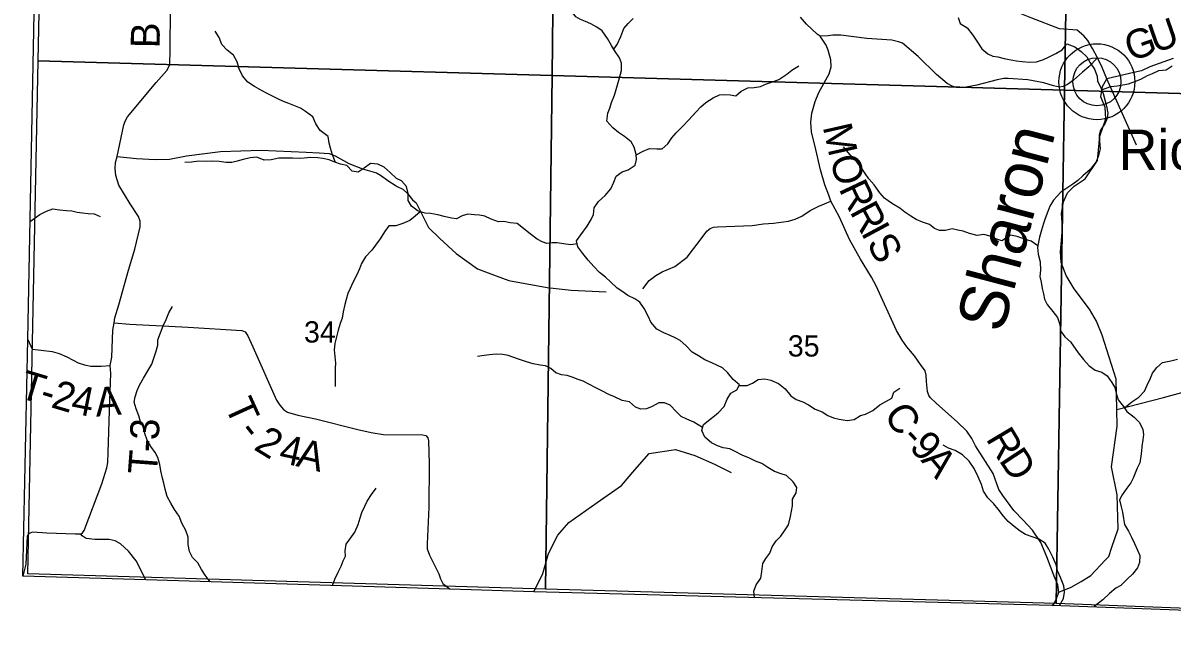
# Model space of a CAD drawing. Extents: x 2043100 to 2470832, y 443715 to 810583.
# Drawn here: x 2209669 to 2221567, y 607335 to 613550 of the extents above; entities that cross this region are included whole.
import ezdxf

# ---------------------------------------------------------------- set-up
doc = ezdxf.new("R2010")
doc.units = 0
for name, color, linetype in [('GM_X_Adjacent_County', 7, 'Continuous'), ('GM_X_County', 7, 'Continuous'), ('GM_X_County_Road', 7, 'Continuous'), ('GM_X_County_Road_Text', 7, 'Continuous'), ('GM_X_Minor_River', 7, 'Continuous'), ('GM_X_Minor_River_Text', 7, 'Continuous'), ('GM_X_Section', 7, 'Continuous'), ('GM_X_Section_Text', 7, 'Continuous'), ('GM_X_Township', 7, 'Continuous'), ('GM_X_Township_Road', 7, 'Continuous'), ('GM_X_Township_Road_Text', 7, 'Continuous'), ('GM_X_Township_ROW', 7, 'Continuous'), ('GM_X_Unincorporated', 7, 'Continuous'), ('GM_X_Unincorporated_Location', 7, 'Continuous'), ('GM_X_Unincorporated_Text', 7, 'Continuous')]:
    doc.layers.add(name, color=color, linetype=linetype)

msp = doc.modelspace()

# ---------------------------------------------------------------- linework, layer by layer
at = {"layer": 'GM_X_Adjacent_County'}
msp.add_lwpolyline([(2223684, 607391), (2220321, 607518), (2214957, 607660), (2214092, 607686), (2210942, 607782), (2209669, 607821), (2209718, 610272), (2209848, 616857), (2209978, 623419), (2210251, 634591)], dxfattribs=at)
at = {"layer": 'GM_X_County'}
msp.add_lwpolyline([(2223684, 607391), (2220321, 607518), (2214957, 607660), (2214092, 607686), (2210942, 607782), (2209669, 607821), (2209718, 610272), (2209848, 616857), (2209978, 623419), (2210251, 634591)], dxfattribs=at)
at = {"layer": 'GM_X_County_Road'}
for points in [[(2220795, 613190), (2220743, 613286), (2220694, 613369), (2220652, 613416), (2220583, 613474), (2220403, 613490), (2220115, 613598), (2219978, 613655), (2219893, 613713), (2219824, 613785), (2219797, 613838), (2219786, 613896), (2219792, 613940), (2219841, 614031), (2220009, 614316), (2220151, 614603), (2220377, 615129), (2220422, 615214), (2220495, 615322), (2220639, 615478), (2220922, 615829), (2220989, 615900), (2221175, 616039), (2221627, 616348)], [(2217922, 613414), (2217894, 613434), (2217783, 613538), (2217720, 613609)], [(2220321, 607518), (2220345, 607536), (2220368, 607584), (2220389, 607633), (2220394, 607654), (2220386, 607731), (2220348, 607819), (2220271, 608021), (2220207, 608169), (2220122, 608298), (2220026, 608400), (2219929, 608500), (2219815, 608657), (2219774, 608719), (2219715, 608885), (2219533, 609171), (2219494, 609248), (2219441, 609323), (2219346, 609414), (2219125, 609611), (2219065, 609666), (2219049, 609690), (2219034, 609733), (2219025, 609835), (2219022, 609903), (2219011, 609947), (2218963, 610014), (2218899, 610103), (2218822, 610194), (2218773, 610265), (2218714, 610366), (2218503, 610827), (2218455, 610918), (2218341, 611104), (2218229, 611306), (2218124, 611538), (2218034, 611705), (2218015, 611765), (2217972, 611872), (2217928, 612029), (2217879, 612240), (2217835, 612421), (2217828, 612523), (2217838, 612617), (2217871, 612737), (2217910, 612829), (2218017, 613024), (2218036, 613094), (2218035, 613168), (2218008, 613269), (2217985, 613319), (2217922, 613414)], [(2220795, 613190), (2220704, 613096), (2220639, 613039), (2220546, 612956), (2220483, 612913), (2220439, 612893), (2220401, 612884), (2220339, 612897), (2220239, 612930), (2220074, 612960), (2219870, 612975), (2219826, 612973), (2219755, 612962), (2219547, 612906), (2219436, 612884), (2219390, 612880), (2219334, 612883), (2219292, 612894), (2219238, 612922), (2219128, 613016), (2218940, 613201), (2218777, 613339), (2218734, 613356), (2218666, 613371), (2218406, 613390), (2218136, 613423), (2218084, 613422), (2218054, 613422), (2218006, 613415), (2217922, 613414)], [(2220892, 612972), (2220842, 613088), (2220795, 613190)], [(2221578, 613180), (2221336, 613094), (2221250, 613055), (2221170, 613036), (2220892, 612972)]]:
    msp.add_lwpolyline(points, dxfattribs=at)
at = {"layer": 'GM_X_Minor_River'}
for points in [[(2215845, 612980), (2215868, 613058), (2215868, 613134), (2215845, 613188), (2215795, 613263), (2215762, 613317), (2215722, 613389), (2215665, 613467), (2215611, 613506), (2215550, 613540), (2215492, 613565), (2215442, 613585), (2215392, 613612), (2215357, 613666), (2215293, 613718), (2215219, 613717), (2215159, 613742), (2215107, 613752), (2215035, 613771), (2214969, 613791), (2214916, 613814), (2214862, 613840), (2214763, 613873)], [(2215786, 613278), (2215820, 613326), (2215859, 613408), (2215889, 613492), (2215936, 613545), (2215986, 613595)], [(2219353, 613605), (2219374, 613543), (2219444, 613499), (2219506, 613424), (2219547, 613362), (2219596, 613282), (2219660, 613229), (2219712, 613207), (2219764, 613198), (2219830, 613180), (2219880, 613171), (2219956, 613159), (2220015, 613152), (2220093, 613142), (2220164, 613147), (2220236, 613170), (2220288, 613194), (2220364, 613233), (2220429, 613272), (2220479, 613334), (2220559, 613303), (2220627, 613255), (2220684, 613200), (2220720, 613136), (2220765, 613070)], [(2212905, 612106), (2212873, 612183), (2212852, 612253), (2212838, 612305), (2212830, 612373), (2212748, 612437), (2212702, 612505), (2212669, 612577), (2212595, 612634), (2212543, 612668), (2212475, 612696), (2212423, 612714), (2212365, 612737), (2212315, 612761), (2212245, 612795), (2212191, 612823), (2212115, 612864), (2212065, 612892), (2211997, 612938), (2211943, 613002), (2211908, 613074), (2211886, 613148), (2211848, 613215), (2211784, 613269), (2211728, 613327), (2211699, 613399), (2211659, 613465)], [(2216018, 612184), (2216092, 612221), (2216157, 612251), (2216233, 612246), (2216287, 612247), (2216347, 612299), (2216386, 612360), (2216434, 612412), (2216499, 612477), (2216564, 612545), (2216636, 612626), (2216689, 612680), (2216741, 612727), (2216816, 612776), (2216880, 612804), (2216938, 612809), (2216990, 612805), (2217052, 612796), (2217107, 612844), (2217175, 612879), (2217239, 612883), (2217307, 612890), (2217367, 612919), (2217440, 612943), (2217496, 612964), (2217578, 613019), (2217629, 613061), (2217701, 613106)], [(2220838, 612858), (2220934, 612891), (2220998, 612900), (2221056, 612909), (2221116, 612919), (2221181, 612942), (2221243, 612968), (2221313, 613005), (2221365, 613027), (2221432, 613058), (2221506, 613063), (2221570, 613105)], [(2217244, 607601), (2217237, 607665), (2217261, 607731), (2217310, 607801), (2217319, 607869), (2217331, 607952), (2217362, 608002), (2217402, 608060), (2217425, 608123), (2217468, 608185), (2217518, 608235), (2217561, 608300), (2217595, 608354), (2217618, 608440), (2217628, 608495), (2217637, 608549), (2217638, 608617), (2217674, 608683), (2217683, 608739), (2217643, 608799), (2217574, 608862), (2217520, 608882), (2217450, 608903), (2217380, 608947), (2217319, 608988), (2217253, 609010), (2217191, 609041), (2217117, 609073), (2217038, 609114), (2216988, 609140), (2216918, 609149), (2216860, 609169), (2216800, 609202), (2216731, 609259), (2216699, 609329), (2216714, 609393), (2216800, 609458), (2216869, 609513), (2216930, 609579), (2216962, 609654), (2216997, 609716), (2217059, 609749), (2217090, 609803), (2217024, 609857), (2216963, 609930), (2216911, 609978), (2216861, 610001), (2216801, 610029), (2216728, 610060), (2216664, 610104), (2216598, 610141), (2216533, 610209), (2216473, 610260), (2216421, 610288), (2216370, 610313), (2216306, 610339), (2216232, 610380), (2216169, 610452), (2216145, 610506), (2216100, 610591), (2216058, 610659), (2216003, 610694), (2215933, 610728), (2215871, 610773), (2215820, 610803), (2215754, 610870), (2215700, 610918), (2215639, 610966), (2215579, 611027), (2215522, 611093), (2215466, 611162), (2215415, 611230), (2215402, 611292), (2215446, 611356), (2215511, 611445), (2215554, 611515), (2215578, 611566), (2215585, 611636), (2215629, 611700), (2215698, 611763), (2215755, 611831), (2215787, 611902), (2215812, 611962), (2215872, 612007), (2215936, 612027), (2216007, 612076), (2216021, 612136), (2216018, 612186), (2215997, 612264), (2215965, 612320), (2215896, 612375), (2215836, 612417), (2215776, 612462), (2215715, 612534), (2215726, 612616), (2215744, 612666), (2215762, 612725), (2215793, 612803), (2215810, 612859), (2215826, 612909), (2215845, 612980)], [(2220765, 613070), (2220793, 612998), (2220796, 612948), (2220826, 612889), (2220853, 612819), (2220871, 612753), (2220888, 612689), (2220901, 612617), (2220897, 612563), (2220876, 612511), (2220828, 612438), (2220811, 612386), (2220815, 612330), (2220824, 612246), (2220807, 612176), (2220781, 612111), (2220720, 612031), (2220645, 611966), (2220593, 611919), (2220539, 611881), (2220478, 611840), (2220414, 611798), (2220339, 611715), (2220300, 611651), (2220280, 611598), (2220255, 611526), (2220235, 611472), (2220214, 611404), (2220194, 611333), (2220183, 611279), (2220175, 611225), (2220182, 611155), (2220203, 611077), (2220205, 610991), (2220198, 610923), (2220213, 610865), (2220221, 610801), (2220236, 610743), (2220248, 610689), (2220273, 610633), (2220331, 610560), (2220380, 610500), (2220406, 610426), (2220411, 610360), (2220457, 610299), (2220514, 610249), (2220595, 610134), (2220649, 610064), (2220708, 609999), (2220772, 609955), (2220840, 609934), (2220897, 609894), (2220943, 609826), (2220974, 609775), (2220988, 609717), (2221009, 609647), (2221065, 609577), (2221100, 609526), (2221174, 609468), (2221229, 609411), (2221263, 609341), (2221272, 609289), (2221266, 609233), (2221253, 609165), (2221251, 609114), (2221244, 609064), (2221232, 608994), (2221207, 608938), (2221185, 608888), (2221166, 608837), (2221142, 608787), (2221099, 608733), (2221049, 608664), (2221024, 608610), (2221041, 608540), (2221055, 608484), (2221064, 608418), (2221076, 608356), (2221115, 608287), (2221147, 608225), (2221178, 608159), (2221208, 608089), (2221233, 608035), (2221229, 607963), (2221208, 607907), (2221157, 607843), (2221101, 607788), (2221038, 607725), (2220986, 607695), (2220919, 607640), (2220849, 607574), (2220760, 607505)], [(2220178, 611243), (2220109, 611289), (2220039, 611310), (2219965, 611339), (2219893, 611351), (2219803, 611294), (2219741, 611313), (2219685, 611341), (2219617, 611358), (2219549, 611348), (2219469, 611369), (2219403, 611393), (2219348, 611404), (2219290, 611418), (2219221, 611399), (2219159, 611402), (2219109, 611422), (2219056, 611462), (2218982, 611485), (2218916, 611514), (2218862, 611548), (2218801, 611590), (2218747, 611631), (2218691, 611667), (2218640, 611698), (2218588, 611736), (2218540, 611792), (2218481, 611873), (2218428, 611935), (2218390, 611990), (2218356, 612042), (2218301, 612114), (2218230, 612189), (2218166, 612267)], [(2214787, 611472), (2214715, 611481), (2214649, 611493), (2214593, 611489), (2214517, 611518), (2214451, 611548), (2214397, 611560), (2214343, 611564), (2214275, 611571), (2214217, 611553), (2214157, 611521), (2214105, 611529), (2214031, 611546), (2213965, 611562), (2213889, 611576), (2213835, 611581), (2213761, 611599), (2213693, 611653), (2213659, 611711), (2213659, 611783), (2213639, 611855), (2213587, 611914), (2213536, 611938), (2213472, 612002), (2213410, 612058), (2213344, 612086), (2213268, 612093), (2213203, 612045), (2213139, 612003), (2213077, 612014), (2213021, 612072), (2212957, 612088), (2212897, 612109), (2212841, 612133), (2212775, 612147), (2212721, 612153), (2212651, 612158), (2212581, 612150), (2212529, 612146), (2212459, 612148), (2212397, 612149), (2212317, 612151), (2212240, 612133), (2212166, 612130), (2212092, 612160), (2212022, 612154), (2211948, 612135), (2211886, 612119), (2211830, 612105), (2211772, 612106), (2211701, 612116), (2211631, 612120), (2211569, 612115), (2211489, 612119), (2211415, 612109), (2211345, 612106)], [(2209746, 611498), (2209843, 611567), (2209911, 611600), (2209977, 611624), (2210047, 611616), (2210121, 611609), (2210175, 611603), (2210229, 611589), (2210285, 611583), (2210345, 611578), (2210405, 611574), (2210467, 611546)], [(2213781, 611594), (2213730, 611549), (2213676, 611503), (2213602, 611472), (2213530, 611450), (2213459, 611450), (2213411, 611385), (2213367, 611315), (2213318, 611247), (2213280, 611197), (2213216, 611126), (2213174, 611058), (2213153, 611004), (2213121, 610934), (2213085, 610862), (2213058, 610800), (2213034, 610749), (2213014, 610685), (2213000, 610633), (2212983, 610557), (2212973, 610491), (2212953, 610437), (2212932, 610367), (2212916, 610299), (2212898, 610231), (2212890, 610164), (2212899, 610094), (2212905, 610028), (2212903, 609974), (2212901, 609908), (2212900, 609858), (2212900, 609784)], [(2215408, 611264), (2215343, 611253), (2215267, 611263), (2215201, 611272), (2215149, 611272), (2215095, 611267), (2215045, 611283), (2214993, 611310), (2214920, 611366), (2214787, 611472)], [(2211607, 607763), (2211556, 607832), (2211519, 607891), (2211479, 607959), (2211425, 608013), (2211393, 608075), (2211381, 608147), (2211380, 608223), (2211356, 608295), (2211314, 608371), (2211286, 608441), (2211237, 608510), (2211199, 608578), (2211163, 608646), (2211143, 608720), (2211128, 608784), (2211114, 608836), (2211098, 608910), (2211086, 608978), (2211064, 609048), (2211037, 609102), (2210993, 609165), (2210955, 609229), (2210931, 609297), (2210921, 609353), (2210886, 609419), (2210868, 609481), (2210840, 609553), (2210822, 609621), (2210831, 609677), (2210851, 609743), (2210875, 609797), (2210917, 609871), (2210962, 609946), (2211004, 610016), (2211024, 610080), (2211045, 610140), (2211065, 610212), (2211065, 610268), (2211092, 610342), (2211120, 610413), (2211150, 610479), (2211179, 610547), (2211217, 610613)], [(2214800, 610067), (2214694, 610107), (2214638, 610116), (2214568, 610120), (2214498, 610114), (2214446, 610106), (2214374, 610095)], [(2216706, 609360), (2216616, 609417), (2216544, 609448), (2216486, 609474), (2216433, 609527), (2216369, 609593), (2216313, 609616), (2216253, 609616), (2216185, 609579), (2216127, 609555), (2216067, 609550), (2216013, 609570), (2215949, 609625), (2215875, 609640), (2215794, 609678), (2215736, 609703), (2215662, 609739), (2215600, 609770), (2215535, 609806), (2215469, 609839), (2215419, 609859), (2215355, 609882), (2215305, 609900), (2215245, 609907), (2215187, 609927), (2215134, 609970), (2215078, 609998), (2215024, 610007), (2214952, 610019), (2214882, 610042), (2214800, 610067)], [(2221074, 609565), (2221151, 609626), (2221222, 609675), (2221282, 609737), (2221311, 609800), (2221343, 609870), (2221366, 609922), (2221408, 609981), (2221467, 610035), (2221553, 610052), (2221625, 610067)], [(2217086, 609796), (2217166, 609794), (2217224, 609818), (2217280, 609857), (2217352, 609865), (2217412, 609852), (2217492, 609817), (2217562, 609759), (2217621, 609688), (2217675, 609650), (2217743, 609627), (2217802, 609595), (2217872, 609550), (2217944, 609524), (2218004, 609485), (2218061, 609461), (2218121, 609448), (2218203, 609432), (2218277, 609443), (2218340, 609486), (2218394, 609498), (2218468, 609537), (2218541, 609595), (2218664, 609665), (2218688, 609725), (2218749, 609769)], [(2220401, 607517), (2220443, 607588), (2220455, 607654), (2220446, 607720), (2220413, 607806), (2220383, 607870), (2220368, 607938), (2220332, 608016), (2220293, 608099), (2220252, 608161), (2220188, 608204), (2220130, 608224), (2220048, 608253), (2219994, 608287), (2219931, 608336), (2219871, 608388), (2219822, 608442), (2219768, 608513), (2219723, 608569), (2219659, 608632), (2219614, 608700), (2219594, 608770), (2219561, 608850), (2219518, 608935), (2219468, 609013), (2219399, 609076), (2219323, 609122), (2219251, 609145), (2219198, 609179)], [(2212875, 607724), (2212898, 607788), (2212931, 607862), (2212965, 607924), (2212985, 607978), (2213007, 608028), (2213006, 608084), (2213016, 608152), (2213070, 608227), (2213106, 608277), (2213139, 608355), (2213159, 608425), (2213177, 608479), (2213210, 608547), (2213234, 608597), (2213278, 608668), (2213327, 608732)]]:
    msp.add_lwpolyline(points, dxfattribs=at)
at = {"layer": 'GM_X_Section'}
for points in [[(2215204, 618338), (2215147, 613006), (2209825, 613158), (2209936, 618484)], [(2215204, 618338), (2220542, 618152), (2220453, 612855), (2215147, 613006)], [(2225918, 617981), (2225830, 612699), (2220453, 612855), (2220542, 618152)], [(2209825, 613158), (2215147, 613006), (2215081, 607686), (2209719, 607845)], [(2215147, 613006), (2220453, 612855), (2220366, 607536), (2215081, 607686)], [(2225830, 612699), (2225736, 607335), (2220366, 607536), (2220453, 612855)]]:
    msp.add_lwpolyline(points, close=True, dxfattribs=at)
at = {"layer": 'GM_X_Township'}
msp.add_lwpolyline([(2223684, 607391), (2220321, 607518), (2214957, 607660), (2214092, 607686), (2210942, 607782), (2209669, 607821), (2209718, 610272), (2209848, 616857), (2209978, 623419), (2210251, 634591)], dxfattribs=at)
at = {"layer": 'GM_X_Township_Road'}
for points in [[(2210612, 610444), (2210612, 610444), (2210620, 610496), (2210660, 610632), (2210762, 610991), (2210826, 611207), (2210883, 611440), (2210882, 611496), (2210864, 611547), (2210780, 611678), (2210662, 611871), (2210631, 611970), (2210624, 612044), (2210628, 612106), (2210643, 612168), (2210713, 612493), (2210731, 612541), (2210752, 612577), (2211048, 612934), (2211157, 613057), (2211181, 613095), (2211188, 613121), (2211193, 613273), (2211198, 613694)], [(2221200, 612283), (2220892, 612972)], [(2210573, 610004), (2210590, 610088), (2210599, 610368), (2210612, 610444)], [(2210612, 610444), (2210776, 610432), (2211379, 610400), (2211934, 610364), (2211968, 610350), (2211996, 610311), (2212048, 610197), (2212294, 609643), (2212327, 609591), (2212365, 609546), (2212409, 609520), (2212516, 609489), (2212698, 609449), (2213136, 609340), (2213276, 609307), (2213402, 609289), (2213811, 609285), (2213839, 609277), (2213861, 609254), (2213867, 609222), (2213874, 608984), (2213873, 608535), (2213853, 608155), (2213854, 608105), (2213879, 608039), (2213975, 607844), (2213993, 607793), (2214016, 607745), (2214092, 607686)], [(2209718, 610272), (2209765, 610171), (2209857, 610160), (2209971, 610147), (2210044, 610128), (2210122, 610093), (2210188, 610056), (2210241, 610030), (2210305, 610009), (2210373, 609996), (2210477, 609997), (2210573, 610004)], [(2210267, 608257), (2210287, 608271), (2210302, 608293), (2210487, 608776), (2210539, 608943), (2210546, 608997), (2210551, 609101), (2210569, 609640), (2210578, 609918), (2210573, 610004)], [(2210267, 608257), (2210213, 608256), (2209916, 608267), (2209768, 608277), (2209750, 608271), (2209730, 608261), (2209713, 608235), (2209698, 607945), (2209669, 607821)], [(2220394, 607654), (2220524, 607708), (2220625, 607767), (2220725, 607826), (2220876, 607985)]]:
    msp.add_lwpolyline(points, dxfattribs=at)
at = {"layer": 'GM_X_Township_ROW'}
for points in [[(2220804, 612234), (2220818, 612378), (2220882, 612558), (2220874, 612674), (2220831, 612783), (2220846, 612890), (2220892, 612972)], [(2210643, 612168), (2210845, 612146), (2211037, 612134), (2211187, 612140), (2211361, 612172), (2211713, 612218), (2212137, 612232), (2212601, 612213), (2212737, 612204), (2212839, 612198), (2212902, 612174), (2213043, 612094), (2213185, 612039), (2213330, 611999), (2213372, 611973), (2213457, 611912), (2213522, 611869), (2213544, 611855), (2213604, 611830), (2213652, 611785), (2213703, 611719), (2213741, 611686), (2213867, 611430), (2213987, 611319), (2214153, 611162), (2214376, 611005), (2214570, 610931), (2214699, 610884), (2215097, 610810), (2215347, 610783), (2215708, 610764)], [(2220876, 607985), (2220914, 608024), (2220945, 608120), (2221008, 608311), (2221000, 608664), (2220940, 608953), (2220999, 609373), (2220995, 609545), (2220987, 609862), (2220843, 610315), (2220785, 610462), (2220712, 610585), (2220553, 610796), (2220470, 610933), (2220420, 611070), (2220413, 611180), (2220428, 611378), (2220431, 611482), (2220422, 611577), (2220444, 611697), (2220483, 611790), (2220554, 611858), (2220669, 611934), (2220794, 612125), (2220804, 612234)], [(2216087, 610796), (2216152, 610881), (2216221, 610936), (2216286, 610974), (2216418, 611026), (2216548, 611123), (2216702, 611327), (2216749, 611393), (2216786, 611422), (2216820, 611434), (2216860, 611439), (2217218, 611453), (2217337, 611471), (2217441, 611476), (2217595, 611498), (2217665, 611517), (2217734, 611550), (2217819, 611608), (2217911, 611654), (2217970, 611678), (2218034, 611705)], [(2220995, 609545), (2221479, 609672), (2222023, 609819), (2222667, 610060), (2222998, 610120), (2223329, 610162), (2223545, 610135), (2224021, 610123)], [(2214957, 607660), (2215053, 607849), (2215112, 608057), (2215206, 608244), (2215320, 608377), (2215615, 608582), (2215867, 608761), (2216005, 608923), (2216152, 609090), (2216424, 609134), (2216626, 609072), (2216829, 608979), (2217002, 608893)], [(2210942, 607782), (2210842, 607981), (2210763, 608078), (2210678, 608157), (2210624, 608188), (2210563, 608200), (2210413, 608202), (2210323, 608211), (2210281, 608237), (2210267, 608257)]]:
    msp.add_lwpolyline(points, dxfattribs=at)
at = {"layer": 'GM_X_Unincorporated'}
for radius in [393, 249]:
    msp.add_circle((2220789, 612941), radius, dxfattribs=at)
at = {"layer": 'GM_X_Unincorporated_Location'}
msp.add_line((2220789, 612941), (2220789, 612941), dxfattribs=at)

# ---------------------------------------------------------------- texts
at = {"layer": 'GM_X_County_Road_Text'}
for s, rotation, p in [('U', 19.1895, (2221388, 613235)), ('G', 19.2056, (2221139, 613148)), ('M', 282.7553, (2217949, 612475)), ('O', 284.8177, (2218023, 612146)), ('R', 295.3436, (2218112, 611834)), ('R', 298.2814, (2218225, 611596)), ('I', 298.2759, (2218341, 611379)), ('S', 298.2737, (2218400, 611271)), ('C', 302.7017, (2218575, 609497)), ('-', 314.7115, (2218751, 609236)), ('9', 313.3512, (2218836, 609150)), ('R', 300.8962, (2219634, 609244)), ('A', 309.6708, (2218959, 609019)), ('D', 303.4023, (2219768, 609021))]:
    msp.add_text(s, height=300, rotation=rotation, dxfattribs=at).set_placement(p)
at = {"layer": 'GM_X_Minor_River_Text'}
msp.add_text('Sharon', height=500.1, rotation=75.2339, dxfattribs=at).set_placement((2219812, 610326))
at = {"layer": 'GM_X_Section_Text'}
for s, p in [('34', (2212579, 610240)), ('35', (2217589, 610095))]:
    msp.add_text(s, height=220.8, rotation=0, dxfattribs=at).set_placement(p)
at = {"layer": 'GM_X_Township_Road_Text'}
for s, rotation, p in [('B', 89.0398, (2211084, 613286)), ('T', 343.2634, (2209613, 609673)), ('2', 343.6829, (2209948, 609572)), ('4', 348.8249, (2210154, 609513)), ('A', 4.8303, (2210427, 609472)), ('-', 343.3419, (2209829, 609608)), ('T', 294.4333, (2211753, 609584)), ('3', 87.8001, (2211076, 609226)), ('-', 307.8358, (2211885, 609314)), ('2', 328.5423, (2212048, 609138)), ('-', 87.6859, (2211071, 609102)), ('4', 347.66, (2212307, 609001)), ('A', 346.4241, (2212486, 608962)), ('T', 85.7318, (2211054, 608867))]:
    msp.add_text(s, height=300, rotation=rotation, dxfattribs=at).set_placement(p)
at = {"layer": 'GM_X_Unincorporated_Text'}
msp.add_text('Rich Valley', height=416.67, rotation=0, dxfattribs=at).set_placement((2221014, 612028))

doc.saveas('drawing.dxf')
